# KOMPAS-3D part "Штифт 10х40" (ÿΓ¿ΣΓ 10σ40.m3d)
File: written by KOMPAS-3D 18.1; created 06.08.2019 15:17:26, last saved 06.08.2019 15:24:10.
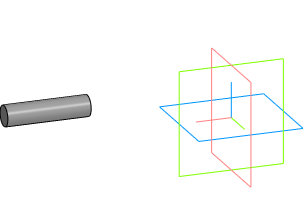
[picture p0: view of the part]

Document properties: Автор: Пользователь Windows; Полное имя файла: D:\Мембранные насосы\Мембранный электропривод\А302-00.00.000 - ASTRA-302 (МЭ200)\3Д ПВХ\Штифт 10х40.m3d

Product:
- Part/product: Штифт 10х40
    Масса: 0.0246804

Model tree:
1. Эскиз:2  (with: Элемент выдавливания:17)  (labels: Штифт 10х40)
2. Элемент выдавливания:1
     Расстояние 2 = 40

Referenced files in D:\Мембранные насосы\Мембранный электропривод\А302-00.00.000 - ASTRA-302 (МЭ200)\3Д ПВХ\: А302-01.10.000 - Рабочая камера.a3d
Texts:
  Крышка рабочей камеры\Крышка\Крышка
